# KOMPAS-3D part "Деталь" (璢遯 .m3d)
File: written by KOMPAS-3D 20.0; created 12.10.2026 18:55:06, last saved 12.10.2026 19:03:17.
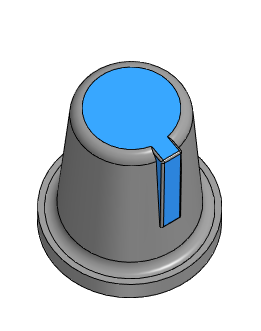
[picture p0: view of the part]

Document properties: Полное имя файла: D:\myProjects\Progect_esp32\box_compas\ручка.m3d

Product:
- Part/product: Деталь
    Масса: 0.0140072

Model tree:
1. Эскиз:1
2. Элемент выдавливания:1
     Расстояние 1 = 2
3. Эскиз:2  (with: Элемент выдавливания:1)
4. Элемент выдавливания:2
     Расстояние 1 = 15
5. Уклон:1  (with: Элемент выдавливания:1, Элемент выдавливания:2)
     Угол уклона = 4
6. Скругление:1  (with: Элемент выдавливания:2)
     Радиус = 1
7. Эскиз:3  (with: Элемент выдавливания:2, Скругление:1)
8. Элемент выдавливания:3
     Расстояние 2 = 10
9. Скругление:2  (with: Элемент выдавливания:3, Элемент выдавливания:2)
     Радиус = 0.2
